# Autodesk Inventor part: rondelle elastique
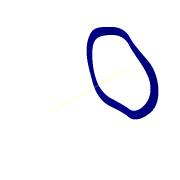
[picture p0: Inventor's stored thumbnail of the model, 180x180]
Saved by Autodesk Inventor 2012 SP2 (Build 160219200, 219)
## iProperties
Created: 2013-04
Part Number: rondelle elastique
Material: Default
Document SubType Name: Modeling
Designer: papa
Density: 1 g/cm^3
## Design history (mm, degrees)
node "rondelle elastique1"
node "Axe de construction1"
node "Plan de construction1"
node "rondelle elastique"
node "Base1"
